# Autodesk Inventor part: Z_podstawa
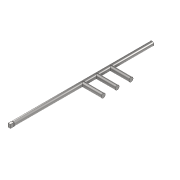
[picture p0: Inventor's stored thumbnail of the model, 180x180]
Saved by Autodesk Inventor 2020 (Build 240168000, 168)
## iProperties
Created: 2021-01
Part Number: Z_podstawa
Material: Stal, węglowa
Document SubType Name: Modeling
Designer: Home
Density: 7.85 g/cm^3
Appearance: Częściowo polerowany
Mass: 74.8577 g
Surface Area: 64.3526 cm^2
Volume: 9.53602 cm^3
Author: Home
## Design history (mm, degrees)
sketch "Szkic1"
  geometry: C1 r 3 at (0, 0); 1 further point
  constraints: 1 centre point, 1 coincident
  dimensions: "d0" = 6 diameter of C1
extrude "Wyciągnięcie proste1" new body sketch "Szkic1" stored distance "d1" = 200; taper "d2" = 0 deg
sketch "Szkic2"
  geometry: L1 (3, -100)-(3, 100) reference; C1 r 3 at (0, 0); C2 r 3 at (0, -20); C3 r 3 at (0, 20); C4 r 3 at (0, 40); C5 r 3 at (0, -40); 1 further point
  constraints: 5 centre point, 4 tangent, 1 coincident
  dimensions: "d3" = 20 distance of C1.centre C3.centre; "d4" = 20 distance of C2.centre C1.centre; "d6" = 20 distance of C3.centre C4.centre; "d7" = 20 distance of C5.centre C2.centre
extrude "Wyciągnięcie proste2" join sketch "Szkic2" distance "d8" = 30; taper "d9" = 0 deg
sketch "Szkic3"
  geometry: L1 (0, 0)-(0, -3); L2 (1.694, 2.476)-(-1.694, 2.476); L3 (-1.694, 2.476)-(-1.694, -2.476); L4 (-1.694, -2.476)-(1.694, -2.476); L5 (1.694, -2.476)-(1.694, 2.476); L6 (1.694, 2.476)-(-1.694, -2.476); L7 (-1.694, 2.476)-(1.694, -2.476); A1 r 3 centre (0, 0) between (0, -3) and (-1.694, -2.476) reference
  constraints: 14 end point, 2 midpoint, 2 parallel, 2 point on circle, 1 horizontal, 1 perpendicular, 1 vertical
extrude "Wyciągnięcie proste3" join sketch "Szkic3" distance "d10" = 5; taper "d11" = 0 deg
node "Bryła1"
